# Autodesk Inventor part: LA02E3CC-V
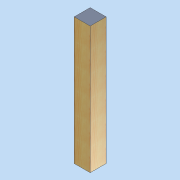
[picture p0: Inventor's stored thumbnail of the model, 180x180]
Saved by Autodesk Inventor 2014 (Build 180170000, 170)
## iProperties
Created: 2013-02
Part Number: LA02E3CC-V
Document SubType Name: Modeling
Designer: david.appleford
Density: 0.44 g/cm^3
Description: Lug End 0.5w 3 Slots
Mass: 1102.73 g
Surface Area: 1566.72 cm^2
Volume: 2506.21 cm^3
Cost Center: £6.00
Material: 000 Redwood
Appearance: Wood (Pine)
Justset: False
Author: david.appleford
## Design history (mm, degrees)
sketch "Sketch1"
  geometry: L1 (0, 0)-(68, 0); L2 (68, 0)-(68, 68); L3 (68, 68)-(0, 68); L4 (0, 68)-(0, 0)
  constraints: 8 end point, 2 parallel, 1 horizontal, 1 perpendicular
  dimensions: "d0" = 68 distance between parallel lines of L2 L4 (= t); "d1" = 68 distance between parallel lines of L1 L3 (= t)
extrude "Extrusion1" new body sketch "Sketch1" distance "d2" = 542; taper "d3" = 0 deg
body "Solid1"
other parameters: "t" = 68 [user parameter; used in 2 equation terms], "Cl" = 2 [user parameter]
